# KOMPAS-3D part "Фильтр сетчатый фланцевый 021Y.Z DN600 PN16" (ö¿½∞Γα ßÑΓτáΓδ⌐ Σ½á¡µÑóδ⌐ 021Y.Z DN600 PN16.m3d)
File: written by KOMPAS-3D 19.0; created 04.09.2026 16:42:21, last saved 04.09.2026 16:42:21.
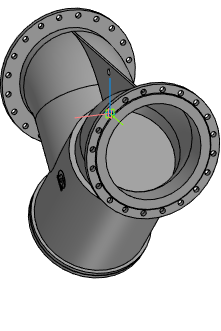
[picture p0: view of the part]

Document properties: Автор: Энергия; Полное имя файла: Z:\3.Личные\sachek\Dendor\_3D для проектировщиков\8.1 Фильтр сетчатый 021Y.Z\021Y.Z_STP\Фильтр сетчатый фланцевый 021Y.Z DN600 PN16.m3d

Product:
- Part/product: Фильтр сетчатый фланцевый 021Y.Z DN600 PN16

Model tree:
1. Операция без истории:1  (labels: Фильтр сетчатый фланцевый 021Y.Z DN600 PN16)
